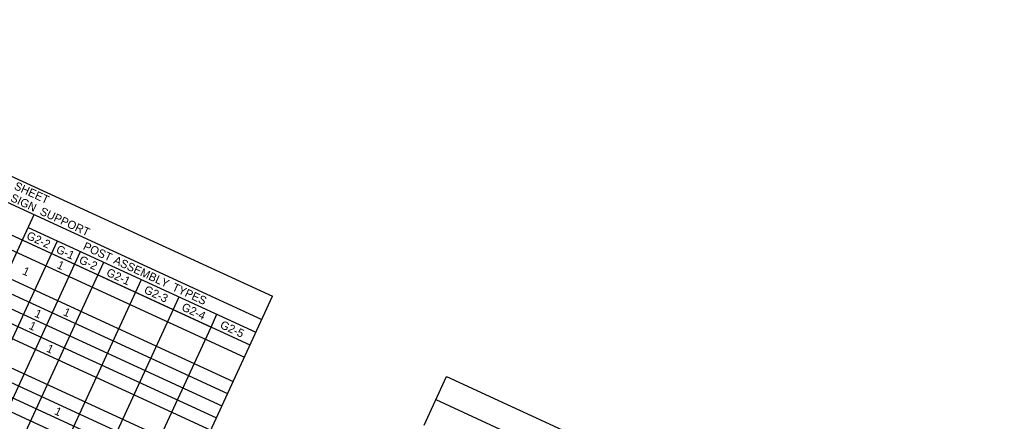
# Model space of a CAD drawing. Extents: x 627405 to 651306, y 367647 to 373471.
# Drawn here: x 650493 to 651034, y 373252 to 373471 of the extents above; entities that cross this region are included whole.
import ezdxf

# ---------------------------------------------------------------- set-up
doc = ezdxf.new("R2010")
doc.units = 0
doc.layers.add('Default', color=7, linetype='Continuous')

msp = doc.modelspace()

# ---------------------------------------------------------------- linework, layer by layer
at = {"layer": 'Default'}
for p, q in [((650303.5, 373471.4), (650631.25, 373320.37)), ((650297.69, 373458.78), (650625.43, 373307.75)), ((650291.26, 373444.83), (650619.01, 373293.81)), ((650291.26, 373444.83), (650597.76, 373303.6)), ((650288.2, 373438.19), (650615.95, 373287.16)), ((650282.08, 373424.91), (650609.83, 373273.88)), ((650279.02, 373418.27), (650606.77, 373267.24)), ((650275.96, 373411.63), (650603.71, 373260.6)), ((650272.9, 373404.99), (650600.65, 373253.96)), ((650269.84, 373398.35), (650597.59, 373247.32)), ((650263.72, 373385.06), (650591.46, 373234.03)), ((650260.66, 373378.42), (650588.4, 373227.39)), ((650257.6, 373371.78), (650585.34, 373220.75)), ((650254.54, 373365.14), (650582.28, 373214.11)), ((650259.47, 372840.32), (650501.24, 373364.98)), ((650259.47, 372840.32), (650498.03, 373358.01)), ((650498.03, 373358.01), (650622.22, 373300.78)), ((650275.41, 372832.97), (650513.97, 373350.66)), ((650288.03, 372827.16), (650526.59, 373344.85)), ((650300.65, 372821.34), (650539.21, 373339.03)), ((650321.24, 372811.86), (650559.79, 373329.55)), ((650341.83, 372802.37), (650580.38, 373320.06)), ((650383.67, 372783.09), (650631.25, 373320.37)), ((650597.76, 373303.6), (650600.97, 373310.57)), ((650362.41, 372792.88), (650597.76, 373303.6)), ((650362.41, 372792.88), (650597.76, 373303.6)), ((650713.97, 373250.05), (650726.21, 373276.61)), ((650726.21, 373276.61), (650726.21, 373276.61)), ((650726.21, 373276.61), (651053.96, 373125.58)), ((650720.39, 373263.99), (651048.14, 373112.97))]:
    msp.add_line(p, q, dxfattribs=at)

# ---------------------------------------------------------------- texts
for s, p in [(' SHEET', (650488.39, 373379.79)), (' SIGN', (650486.37, 373373.29)), (' SUPPORT', (650502.41, 373365.9)), ('G2-2', (650496.65, 373351.94)), ('POST', (650527.55, 373346.15)), ('G-1', (650512.81, 373344.49)), ('1', (650513.29, 373336.02)), ('G-2', (650525.33, 373338.72)), (' ASSEMBLY', (650542.58, 373339.23)), ('1', (650494.42, 373332.64)), ('G2-1', (650540.24, 373331.85)), ('G2-3', (650560.79, 373322.38)), (' TYPES', (650574.56, 373324.49)), ('1', (650501.04, 373309.46)), ('1', (650516.72, 373310.28)), ('G2-4', (650581.3, 373312.93)), ('G2-5', (650602.29, 373303.26)), ('1', (650497.98, 373302.81)), ('1', (650507.54, 373290.36)), ('1', (650511.9, 373256.14))]:
    msp.add_text(s, height=4.5, rotation=335.2593, dxfattribs=at).set_placement(p)

doc.saveas('drawing.dxf')
